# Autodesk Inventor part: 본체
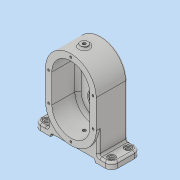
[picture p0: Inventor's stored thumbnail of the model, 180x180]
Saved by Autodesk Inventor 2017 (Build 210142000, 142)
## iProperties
Part Number: 본체
Material: 일반
Document SubType Name: Modeling
Designer: MRC
Density: 1 g/cm^3
Appearance: 기본값
Author: MRC
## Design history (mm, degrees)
sketch "스케치1"
  geometry: L1 (0, 0)-(0, -45); L2 (-40, 0)-(-40, -45); L3 (40, -45)-(40, 0); A1 r 40 centre (0, 0) between (40, 0) and (-40, 0); A2 r 40 centre (0, -45) between (-40, -45) and (40, -45); 2 further points
  constraints: 8 end point, 4 point on circle, 4 tangent, 2 centre point, 1 coincident, 1 midpoint, 1 parallel, 1 vertical
  dimensions: "d1" = 80 distance between parallel lines of L2 L3; "d2" = 45 distance of L1.start L1.end
extrude "돌출1" new body sketch "스케치1" distance "d3" = 49; taper "d4" = 0 deg
feature "쉘1" dims "d5" = 8, "d6" = 10
sketch "스케치2"
  geometry: L1 (0, 0)-(0, -45); L2 (-26, 0)-(-26, -45); L3 (26, -45)-(26, 0); A1 r 26 centre (0, 0) between (26, 0) and (-26, 0); A2 r 26 centre (0, -45) between (-26, -45) and (26, -45); 1 further point
  constraints: 8 end point, 4 point on circle, 4 tangent, 2 centre point, 1 midpoint, 1 parallel, 1 vertical
  dimensions: "d7" = 52 distance between parallel lines of L2 L3; "d8" = 45 distance of L1.start L1.end
extrude "돌출2" join sketch "스케치2" distance "d9" = 11; taper "d10" = 0 deg
sketch "스케치3"
  geometry: L1 (-26, 0)-(-26, -45) reference; L2 (26, -45)-(26, 0) reference; L3 (-26, -30)-(26, -30); A1 r 26 centre (0, -45) between (-26, -45) and (26, -45) reference; A2 r 26 centre (0, 0) between (26, 0) and (-26, 0) reference; 1 further point
  constraints: 2 end point, 2 point on line, 1 horizontal
  dimensions: "d11" = 30 distance from line of L3 point (0, 0)
extrude "돌출3" cut sketch "스케치3" distance "d12" = 3; taper "d13" = 0 deg
hole "구멍1" diameter "d16" = 22; stored, may be unused: countersink angle "d20" = 90 deg, drill point angle "d22" = 118 deg; dims "d14" = 10, "d15" = 10, "d17" = 6, "d18" = 28, "d19" = 4, "d21" = 8
sketch "스케치4"
  geometry: C1 r 14 at (0, 45); 1 further point
  constraints: 1 centre point, 1 coincident
  dimensions: "d23" = 28 diameter of C1
extrude "돌출4" cut sketch "스케치4" distance "d24" = 8; taper "d25" = 0 deg
hole "구멍2" diameter "d28" = 20; stored, may be unused: countersink angle "d32" = 90 deg, drill point angle "d34" = 0 deg; dims "d29" = 6, "d30" = 28, "d31" = 8, "d33" = 12, "d149" = 10, "d150" = 10
node "작업 평면3"
  node "작업 평면2"
sketch "스케치5"
  geometry: C1 r 6 at (0, -21); 1 further point
  constraints: 1 centre point, 1 vertical alignment
  dimensions: "d37" = 12 diameter of C1; "d38" = 21 distance of C1.centre point (0, 0)
extrude "돌출5" join sketch "스케치5" stored distance "d39" = 8; taper "d40" = 0 deg
hole "구멍3" diameter "d43" = 4.917; stored, may be unused: countersink angle "d47" = 90 deg, drill point angle "d49" = 0 deg; dims "d41" = 10, "d42" = 10, "d44" = 12, "d45" = 28, "d46" = 4, "d48" = 17.1
sketch "스케치6"
  geometry: 2 further points
  constraints: 1 vertical alignment
  dimensions: "d50" = 20 distance of point (0, 20) point (0, 0)
hole "구멍4" sketch "스케치6" at (0, 20) diameter "d51" = 3.242; stored, may be unused: countersink angle "d55" = 90 deg, drill point angle "d57" = 118 deg; dims "d52" = 8, "d53" = 28, "d54" = 4, "d56" = 10
sketch "스케치7"
  geometry: L1 (-40, -82)-(-61, -82); L2 (-61, -82)-(-61, -92); L3 (-61, -92)-(-35, -92); L4 (-35, -92)-(-35, -87); L5 (-35, -87)-(35, -87); L6 (35, -87)-(35, -92); L7 (35, -92)-(61, -92); L8 (61, -92)-(61, -82); L9 (61, -82)-(40, -82); L10 (-40, -82)-(-40, -45); L11 (40, -82)-(40, -45); L12 (-40, 0)-(-40, -45) reference; L13 (40, -45)-(40, 0) reference; A1 r 40 centre (0, -45) between (-40, -45) and (40, -45) reference; A2 r 26 centre (0, -45) between (-26, -45) and (26, -45) reference; 2 further points
  constraints: 22 end point, 6 perpendicular, 4 point on line, 3 collinear, 2 point on circle, 2 vertical, 1 horizontal, 1 midpoint, 1 vertical alignment
  dimensions: "d62" = 70 distance of L4.end L5.end; "d63" = 5 distance between parallel lines of L3 L5; "d64" = 122 distance between parallel lines of L8 L2; "d65" = 10 distance of L1.end L2.end; "d66" = 47 distance from line of A2.centre L3
extrude "돌출6" join sketch "스케치7" distance "d67" = 46; taper "d68" = 0 deg
fillet "모깎기1" dims "d69" = 10
hole "구멍5" diameter "d72" = 6.6; stored, may be unused: countersink angle "d76" = 90 deg, drill point angle "d78" = 118 deg; dims "d70" = 10, "d71" = 10, "d73" = 6.6, "d74" = 11, "d75" = 2, "d77" = 10
hole "구멍6" diameter "d81" = 6.6; stored, may be unused: countersink angle "d85" = 90 deg, drill point angle "d87" = 118 deg; dims "d79" = 10, "d80" = 10, "d82" = 6.6, "d83" = 11, "d84" = 2, "d86" = 10
hole "구멍7" diameter "d90" = 6.6; stored, may be unused: countersink angle "d94" = 90 deg, drill point angle "d96" = 118 deg; dims "d88" = 10, "d89" = 10, "d91" = 6.6, "d92" = 11, "d93" = 2, "d95" = 10
hole "구멍8" diameter "d99" = 6.6; stored, may be unused: countersink angle "d103" = 90 deg, drill point angle "d105" = 118 deg; dims "d97" = 10, "d98" = 10, "d100" = 6.6, "d101" = 11, "d102" = 2, "d104" = 10
sketch "스케치9"
  geometry: C1 r 14 at (0, 0) reference; C2 r 14 at (0, -45) reference; 7 further points
  constraints: 4 horizontal alignment, 2 vertical alignment
  dimensions: "d116" = 34.99967 distance of C2.centre point (35, -45); "d117" = 35 distance of C2.centre point (0, -80); "d118" = 35 distance of C2.centre point (-35, -45); "d119" = 35 distance of point (0, 0) point (-35, 0); "d120" = 35 distance of point (0, 0) point (0, 35); "d121" = 34.99967 distance of point (35, 0) point (0, 0)
hole "구멍10" sketch "스케치9" at (0, -80), (35, -45), (35, 0), (0, 35), (-35, 0), (-35, -45) diameter "d122" = 3.242; stored, may be unused: countersink angle "d126" = 90 deg, drill point angle "d128" = 118 deg; dims "d123" = 8, "d124" = 11, "d125" = 2, "d127" = 10
sketch "스케치10"
  geometry: 2 further points
  constraints: 1 vertical alignment
  dimensions: "d129" = 21 distance of point (35, 49) point (35, 28)
hole "구멍11" sketch "스케치10" at (35, 28) diameter "d130" = 4.917; stored, may be unused: countersink angle "d134" = 90 deg, drill point angle "d136" = 0 deg; dims "d131" = 12, "d132" = 12, "d133" = 1, "d135" = 17.1
sketch "스케치11"
  geometry: L1 (-51, -92)-(-61, -92) reference; 2 further points
  constraints: 1 vertical alignment, 1 other
  dimensions: "d137" = 12 distance from line of point (0, -80) L1
feature "엠보싱1" sketch "스케치11" dims "d1" = 80, "d2" = 45, "d138" = 0.5, "d139" = 0
fillet "모깎기2" dims "d140" = 3
fillet "모깎기3" dims "d141" = 3
fillet "모깎기4" dims "d142" = 3
fillet "모깎기5" dims "d143" = 5
chamfer "모따기1" distance "d144" = 1; stored, may be unused: second distance "d145" = 2, angle "d146" = 45 deg
fillet "모깎기6" dims "d147" = 0.3
fillet "모깎기7" dims "d148" = 3
node "솔리드1"
pattern_circular "원형 패턴1" dims angle "d59" = 360 deg
node "투영된 루프1"
other parameters: "d36" = 3
